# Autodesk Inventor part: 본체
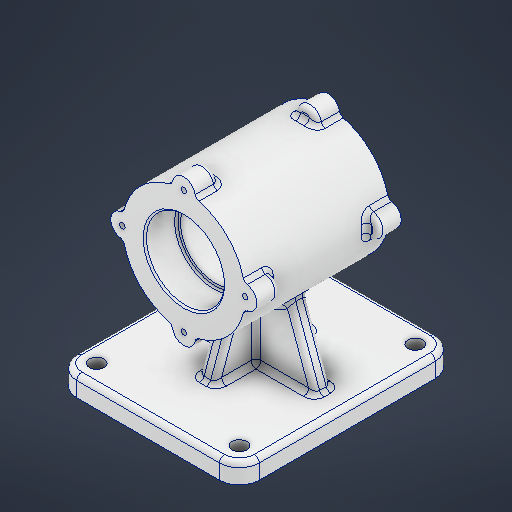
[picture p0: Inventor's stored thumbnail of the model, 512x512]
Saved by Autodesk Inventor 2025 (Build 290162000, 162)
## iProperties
Created: 2025-08
Part Number: 본체
Material: 알루미늄 6061
Document SubType Name: Modeling
Designer: infra027
Density: 2.7 g/cm^3
Appearance: 알루미늄 - 평지
Author: infra027
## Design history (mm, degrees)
sketch "스케치1"
  geometry: L1 (55, -65)-(-55, -65); L2 (-55, -65)-(-55, 65); L3 (-55, 65)-(55, 65); L4 (55, 65)-(55, -65); L5 (55, -65)-(-55, 65); L6 (-55, -65)-(55, 65); L7 (43, 53)-(-43, 53); L8 (-43, 53)-(-43, -53); L9 (-43, -53)-(43, -53); L10 (43, -53)-(43, 53); L11 (43, 53)-(-43, -53); L12 (-43, 53)-(43, -53); C1 r 4.5 at (43, -53); C2 r 4.5 at (-43, 53); C3 r 4.5 at (-43, -53); C4 r 4.5 at (43, 53); 1 further point
  constraints: 25 end point, 4 centre point, 4 midpoint, 4 parallel, 3 coincident, 2 horizontal, 2 perpendicular
  dimensions: "d0" = 130 distance between parallel lines of L1 L3; "d1" = 110 distance between parallel lines of L2 L4; "d2" = 86 distance of L9.end L8.end; "d3" = 106 distance of L8.end L7.end; "d4" = 9 diameter of C1; "d5" = 9 diameter of C2; "d6" = 9 diameter of C3; "d7" = 9 diameter of C4
extrude "돌출1" new body sketch "스케치1" distance "d8" = 12; taper "d9" = 0 deg
sketch "스케치2"
  geometry: L1 (82, 43.5)-(105.5, 43.5); L2 (105.5, 43.5)-(105.5, 24.5); L3 (105.5, 24.5)-(82, 24.5); L4 (82, 24.5)-(82, 43.5); L5 (0, 65)-(0, -65) reference; L6 (82, 24.5)-(103, 24.5); L7 (103, 24.5)-(103, -24.5); L8 (103, -24.5)-(82, -24.5); L9 (82, -24.5)-(82, 24.5); L10 (82, -24.5)-(105.5, -24.5); L11 (105.5, -24.5)-(105.5, -43.5); L12 (105.5, -43.5)-(82, -43.5); L13 (82, -43.5)-(82, -24.5); L14 (82, 43.5)-(119, 43.5); L15 (119, 43.5)-(119, -43.5); L16 (119, -43.5)-(82, -43.5); L17 (82, -43.5)-(82, 43.5); 7 further points
  constraints: 32 end point, 8 parallel, 4 horizontal, 4 perpendicular, 2 midpoint
  dimensions: "d10" = 82 distance between parallel lines of L5 L4; "d11" = 19 distance between parallel lines of L3 L14; "d12" = 19 distance between parallel lines of L12 L10; "d13" = 87 distance between parallel lines of L16 L14; "d14" = 0 vertical distance of point (82, 0) point (0, 0); "d15" = 23.5 distance between parallel lines of L4 L2; "d16" = 23.5 distance between parallel lines of L13 L11 (= d15); "d17" = 21 distance between parallel lines of L9 L7; "d18" = 37 distance between parallel lines of L9 L15
revolve "회전1" sketch "스케치2" stored, may be unused: angle "d19" = 90 deg
sketch "스케치3"
  geometry: C1 r 7 at (0, 37); C2 r 7 at (37, 0); C3 r 7 at (0, -37); C4 r 7 at (-37, 0); A1 r 37 centre (0, 0) between (0, 37) and (37, 0) reference; 9 further points
  constraints: 4 centre point, 4 point on circle, 2 horizontal alignment, 2 vertical alignment
  dimensions: "d20" = 14 diameter of C1; "d21" = 14 diameter of C2; "d22" = 14 diameter of C3; "d23" = 14 diameter of C4
extrude "돌출2" join sketch "스케치3" distance "d24" = 14; taper "d25" = 0 deg
sketch "스케치4"
  geometry: A1 r 37 centre (0, 37) between (6.969, 73.338) and (-6.969, 73.338) reference; A2 r 7 centre (0, 74) between (6.969, 73.338) and (-6.969, 73.338) reference; A3 r 7 centre (37, 37) between (36.338, 30.031) and (36.338, 43.969) reference; A4 r 37 centre (0, 37) between (36.338, 30.031) and (36.338, 43.969) reference; A5 r 7 centre (0, 0) between (-6.969, 0.662) and (6.969, 0.662) reference; A6 r 37 centre (0, 37) between (-6.969, 0.662) and (6.969, 0.662) reference; A7 r 7 centre (-37, 37) between (-36.338, 43.969) and (-36.338, 30.031) reference; A8 r 37 centre (0, 37) between (-36.338, 43.969) and (-36.338, 30.031) reference; 1 further point
hole "구멍1" sketch "스케치4" at (0, 74), (37, 37), (0, 0), (-37, 37) diameter "d26" = 3.242; stored, may be unused: countersink angle "d30" = 90 deg, drill point angle "d32" = 118 deg; dims "d27" = 8, "d28" = 4, "d29" = 2, "d31" = 10
sketch "스케치12"
  geometry: L1 (45, -29.5)-(45, 29.5) reference; L2 (45, 17.989)-(12, 30); L3 (12, 65)-(12, -65) reference; L4 (45, -17.989)-(12, -30); L5 (45, 0)-(12, 0); 1 further point
  constraints: 6 end point, 4 point on line, 2 midpoint, 1 horizontal
  dimensions: "d72" = 110 deg angle of L3 L2; "d73" = 60 distance of L4.end L2.end; "d74" = 110 deg angle of L3 L4; "d75" = 30 distance of L4.end L5.end
sketch "스케치13"
  geometry: L1 (-5, -5)-(5, -5); L2 (5, -5)-(5, 5); L3 (5, 5)-(-5, 5); L4 (-5, 5)-(-5, -5); L5 (-5, -5)-(5, 5); L6 (5, -5)-(-5, 5); 1 further point
  constraints: 12 end point, 2 midpoint, 2 parallel, 1 horizontal, 1 perpendicular
  dimensions: "d76" = 10 distance of L3.end L2.end; "d77" = 10 distance of L2.end L1.end
extrude "돌출5" join sketch "스케치13" stored distance "d78" = 10; taper "d79" = 0 deg
feature "리브3" dims "d80" = 1, "d81" = 10, "d82" = 0, "d83" = 0, "d84" = 1, "d85" = 1
feature "리브4" dims "d86" = 1, "d87" = 10, "d88" = 0, "d89" = 0, "d90" = 1, "d91" = 1
sketch "스케치14"
  geometry: L1 (25.336, 55.036)-(41, 12); L2 (38.5, 12)-(47.5, 12) reference; L3 (55, 0)-(55, 12) reference; L4 (-55, 12)-(55, 12) reference; L5 (-25.336, 55.036)-(-41, 12); L6 (-55, 0)-(-55, 12) reference; A1 r 37 centre (0, 82) between (6.969, 45.662) and (36.338, 75.031) reference; A2 r 37 centre (0, 82) between (-36.338, 75.031) and (-6.969, 45.662) reference; 1 further point
  constraints: 4 end point, 2 point on circle, 2 point on line
  dimensions: "d92" = 14 distance from line of L1.end L3; "d93" = 110 deg angle of L4 L1; "d94" = 14 distance from line of L6 L5.end; "d95" = 110 deg angle of L4 L5
feature "리브5" dims "d96" = 1, "d97" = 10, "d98" = 0, "d99" = 0, "d100" = 1, "d101" = 1
feature "리브6" dims "d102" = 1, "d103" = 10, "d104" = 0, "d105" = 0, "d106" = 1, "d107" = 1
fillet "모깎기1" dims "d108" = 12
fillet "모깎기2" dims "d109" = 3
fillet "모깎기3" dims "d110" = 3
fillet "모깎기4" dims "d111" = 3
fillet "모깎기5" dims "d112" = 1
chamfer "모따기1" distance "d113" = 1; stored, may be unused: second distance "d114" = 2, angle "d115" = 45 deg
chamfer "모따기2" distance "d116" = 1; stored, may be unused: second distance "d117" = 2, angle "d118" = 45 deg
node "솔리드1"
mirror "미러1"
mirror "미러2"
feature "A9D066F2-1C7D-4E18-AEED-F7BC21143FA4" dims "d26" = 3.242, "d27" = 8, "d28" = 4, "d29" = 2, "d30" = 90 deg, "d31" = 10, "d32" = 118 deg
